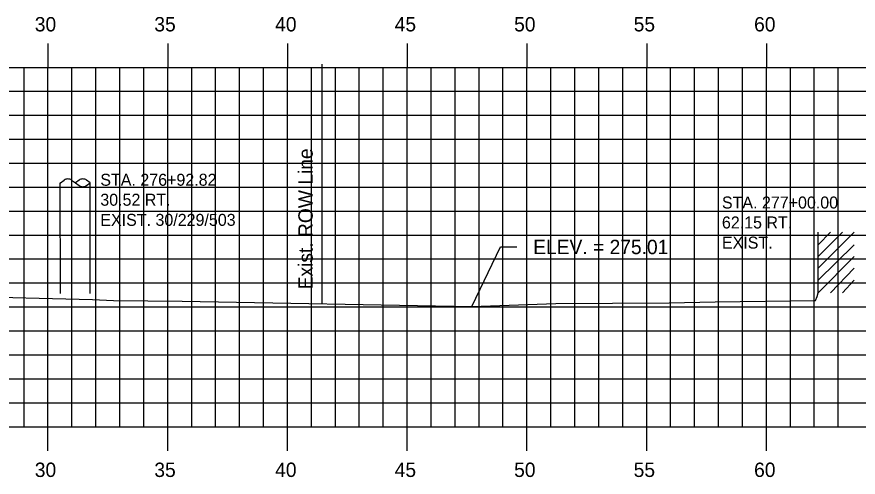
# Model space of a CAD drawing. Extents: x 854008 to 854178, y 366268 to 366378.
# Drawn here: x 854119.8 to 854154.93, y 366300.13 to 366319.35 of the extents above; entities that cross this region are included whole.
import ezdxf

# ---------------------------------------------------------------- set-up
doc = ezdxf.new("R2010")
doc.units = 0
for name, color, linetype in [('D_Text_Monospaced', 7, 'Continuous'), ('D_Text_Standard', 7, 'Continuous'), ('E_ROW_Line', 7, 'Continuous'), ('H_V ANNOTATION', 7, 'Continuous'), ('MAJOR', 7, 'Continuous'), ('MINOR', 7, 'Continuous'), ('S_Buildings', 7, 'Continuous'), ('S_Roadway_Centerline', 7, 'Continuous'), ('S_Utilities_Pole_Power', 7, 'Continuous')]:
    doc.layers.add(name, color=color, linetype=linetype)

msp = doc.modelspace()

# ---------------------------------------------------------------- linework, layer by layer
at = {"layer": 'D_Text_Standard'}
msp.add_lwpolyline([(854138.808, 366307.246), (854140.005, 366309.738), (854140.685, 366309.738)], dxfattribs=at)
at = {"layer": 'E_ROW_Line'}
msp.add_line((854132.557, 366307.368), (854132.557, 366317.368), dxfattribs=at)
at = {"layer": 'MAJOR'}
for p, q in [((854121.103, 366318.238), (854121.103, 366317.236)), ((854126.103, 366318.238), (854126.103, 366317.236)), ((854131.103, 366318.238), (854131.103, 366317.236)), ((854136.103, 366318.238), (854136.103, 366317.236)), ((854141.103, 366318.238), (854141.103, 366317.236)), ((854146.103, 366318.238), (854146.103, 366317.236)), ((854151.103, 366318.238), (854151.103, 366317.236)), ((854021.103, 366317.236), (854161.103, 366317.236)), ((854021.103, 366317.236), (854161.103, 366317.236)), ((854121.103, 366302.236), (854121.103, 366317.236)), ((854126.103, 366302.236), (854126.103, 366317.236)), ((854131.103, 366302.236), (854131.103, 366317.236)), ((854136.103, 366302.236), (854136.103, 366317.236)), ((854141.103, 366302.236), (854141.103, 366317.236)), ((854146.103, 366302.236), (854146.103, 366317.236)), ((854151.103, 366302.236), (854151.103, 366317.236)), ((854021.103, 366312.236), (854161.103, 366312.236)), ((854021.103, 366307.236), (854161.103, 366307.236)), ((854021.103, 366302.236), (854161.103, 366302.236)), ((854021.103, 366302.236), (854161.103, 366302.236)), ((854121.103, 366301.234), (854121.103, 366302.236)), ((854126.103, 366301.234), (854126.103, 366302.236)), ((854131.103, 366301.234), (854131.103, 366302.236)), ((854136.103, 366301.234), (854136.103, 366302.236)), ((854141.103, 366301.234), (854141.103, 366302.236)), ((854146.103, 366301.234), (854146.103, 366302.236)), ((854151.103, 366301.234), (854151.103, 366302.236))]:
    msp.add_line(p, q, dxfattribs=at)
at = {"layer": 'MINOR'}
for p, q in [((854120.103, 366302.236), (854120.103, 366317.236)), ((854122.103, 366302.236), (854122.103, 366317.236)), ((854123.103, 366302.236), (854123.103, 366317.236)), ((854124.103, 366302.236), (854124.103, 366317.236)), ((854125.103, 366302.236), (854125.103, 366317.236)), ((854127.103, 366302.236), (854127.103, 366317.236)), ((854128.103, 366302.236), (854128.103, 366317.236)), ((854129.103, 366302.236), (854129.103, 366317.236)), ((854130.103, 366302.236), (854130.103, 366317.236)), ((854132.103, 366302.236), (854132.103, 366317.236)), ((854133.103, 366302.236), (854133.103, 366317.236)), ((854134.103, 366302.236), (854134.103, 366317.236)), ((854135.103, 366302.236), (854135.103, 366317.236)), ((854137.103, 366302.236), (854137.103, 366317.236)), ((854138.103, 366302.236), (854138.103, 366317.236)), ((854139.103, 366302.236), (854139.103, 366317.236)), ((854140.103, 366302.236), (854140.103, 366317.236)), ((854142.103, 366302.236), (854142.103, 366317.236)), ((854143.103, 366302.236), (854143.103, 366317.236)), ((854144.103, 366302.236), (854144.103, 366317.236)), ((854145.103, 366302.236), (854145.103, 366317.236)), ((854147.103, 366302.236), (854147.103, 366317.236)), ((854148.103, 366302.236), (854148.103, 366317.236)), ((854149.103, 366302.236), (854149.103, 366317.236)), ((854150.103, 366302.236), (854150.103, 366317.236)), ((854152.103, 366302.236), (854152.103, 366317.236)), ((854153.103, 366302.236), (854153.103, 366317.236)), ((854154.103, 366302.236), (854154.103, 366317.236)), ((854021.103, 366316.236), (854161.103, 366316.236)), ((854021.103, 366315.236), (854161.103, 366315.236)), ((854021.103, 366314.236), (854161.103, 366314.236)), ((854021.103, 366313.236), (854161.103, 366313.236)), ((854021.103, 366311.236), (854161.103, 366311.236)), ((854021.103, 366310.236), (854161.103, 366310.236)), ((854021.103, 366309.236), (854161.103, 366309.236)), ((854021.103, 366308.236), (854161.103, 366308.236)), ((854021.103, 366306.236), (854161.103, 366306.236)), ((854021.103, 366305.236), (854161.103, 366305.236)), ((854021.103, 366304.236), (854161.103, 366304.236)), ((854021.103, 366303.236), (854161.103, 366303.236))]:
    msp.add_line(p, q, dxfattribs=at)
at = {"layer": 'S_Buildings'}
for p, q in [((854153.258, 366307.83), (854153.258, 366310.356)), ((854153.258, 366308.847), (854154.767, 366310.356)), ((854153.258, 366309.339), (854154.275, 366310.356)), ((854153.258, 366309.831), (854153.782, 366310.356)), ((854153.258, 366308.355), (854154.767, 366309.831)), ((854153.258, 366307.83), (854154.767, 366309.339)), ((854153.782, 366307.83), (854154.767, 366308.847)), ((854154.275, 366307.83), (854154.767, 366308.355))]:
    msp.add_line(p, q, dxfattribs=at)
at = {"layer": 'S_Roadway_Centerline'}
msp.add_lwpolyline([(854117.398, 366307.685), (854122.963, 366307.541), (854123.837, 366307.5), (854126.708, 366307.481), (854138.808, 366307.246), (854142.315, 366307.384), (854147.047, 366307.402), (854148.966, 366307.453), (854153.154, 366307.499), (854153.226, 366307.667), (854153.258, 366307.83)], dxfattribs=at)
at = {"layer": 'S_Utilities_Pole_Power'}
for p, q in [((854121.621, 366307.796), (854121.618, 366312.416)), ((854121.621, 366312.416), (854121.777, 366312.526)), ((854122.09, 366312.526), (854122.246, 366312.416)), ((854122.403, 366312.526), (854122.246, 366312.416)), ((854122.246, 366312.416), (854122.403, 366312.305)), ((854122.871, 366312.416), (854122.715, 366312.526)), ((854122.715, 366312.305), (854122.871, 366312.416)), ((854122.871, 366307.796), (854122.868, 366312.416))]:
    msp.add_line(p, q, dxfattribs=at)
for centre, start, end in [((854121.934, 366312.305), 90, 125.2644), ((854121.934, 366312.305), 54.7356, 90), ((854122.559, 366312.305), 90, 125.2644), ((854122.559, 366312.305), 54.7356, 90), ((854122.559, 366312.526), 234.7356, 270), ((854122.559, 366312.526), 270, 305.2644)]:
    msp.add_arc(centre, 0.271, start, end, dxfattribs=at)

# ---------------------------------------------------------------- texts
at = {"layer": 'D_Text_Monospaced'}
for s, height, p in [('STA. 276+92.82', 0.49998, (854123.288, 366312.294)), ('30.52 RT.', 0.5, (854123.288, 366311.46)), ('STA. 277+00.00', 0.49998, (854149.245, 366311.344)), ('EXIST. 30/229/503', 0.49998, (854123.288, 366310.62)), ('62.15 RT.', 0.5, (854149.245, 366310.51)), ('EXIST. ', 0.5, (854149.245, 366309.67))]:
    msp.add_text(s, height=height, dxfattribs=at).set_placement(p)
at = {"layer": 'D_Text_Standard'}
msp.add_text('ELEV. = 275.01', height=0.6, dxfattribs=at).set_placement((854141.365, 366309.438))
at = {"layer": 'E_ROW_Line'}
msp.add_text('Exist. ROW Line', height=0.6, rotation=90, dxfattribs=at).set_placement((854132.157, 366307.968))
at = {"layer": 'H_V ANNOTATION'}
for s, p in [('30', (854120.552, 366318.736)), ('35', (854125.544, 366318.736)), ('40', (854130.589, 366318.736)), ('45', (854135.581, 366318.736)), ('50', (854140.568, 366318.736)), ('55', (854145.56, 366318.736)), ('60', (854150.589, 366318.736)), ('30', (854120.552, 366300.136)), ('35', (854125.544, 366300.136)), ('40', (854130.589, 366300.136)), ('45', (854135.581, 366300.136)), ('50', (854140.568, 366300.136)), ('55', (854145.56, 366300.136)), ('60', (854150.589, 366300.136))]:
    msp.add_text(s, height=0.6, dxfattribs=at).set_placement(p)

doc.saveas('drawing.dxf')
